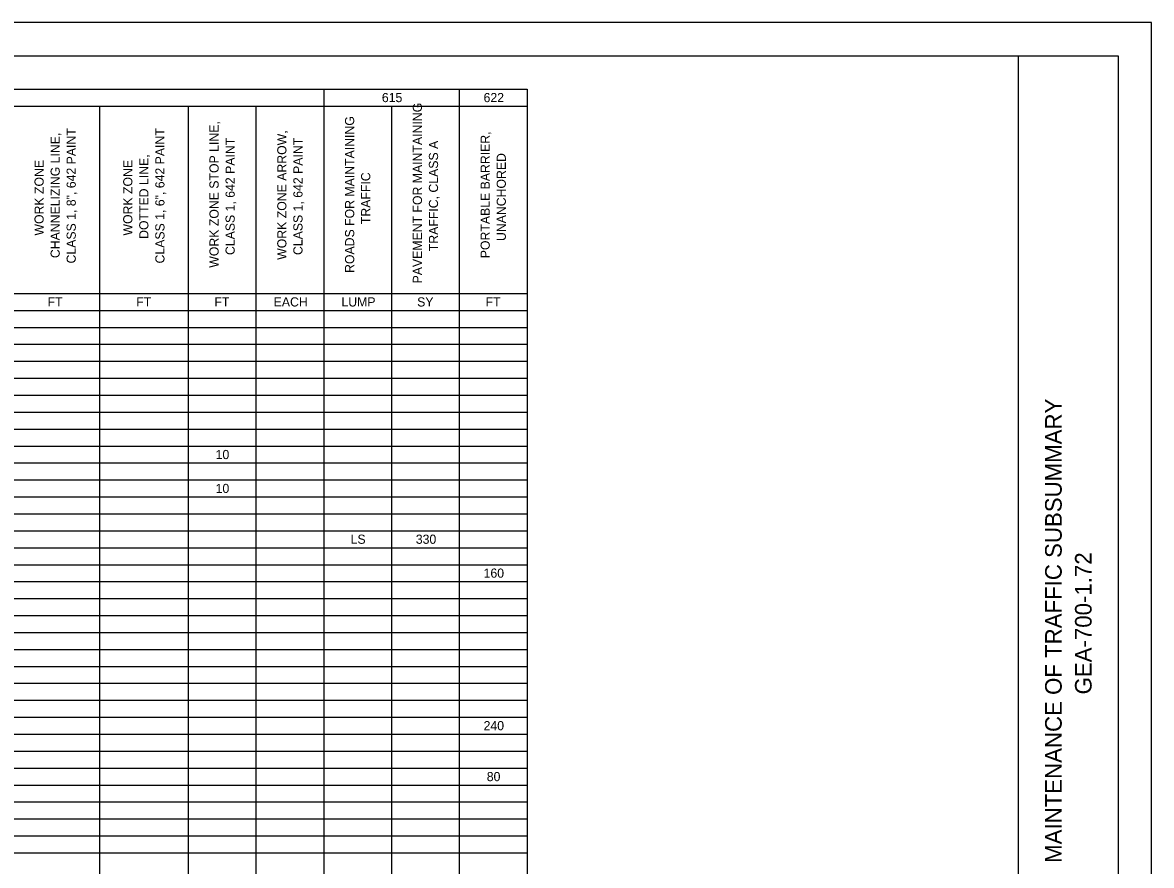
# Model space of a CAD drawing. Extents: x 0 to 34, y 0 to 22.
# Drawn here: x 17.01 to 34, y 9.32 to 22 of the extents above; entities that cross this region are included whole.
import ezdxf

# ---------------------------------------------------------------- set-up
doc = ezdxf.new("R2010")
doc.units = 0
for name, color, linetype in [('SH_Border', 7, 'Continuous'), ('SH_Cut_Line', 7, 'Continuous'), ('SH_Data', 7, 'Continuous'), ('SH_Text', 7, 'Continuous')]:
    doc.layers.add(name, color=color, linetype=linetype)

msp = doc.modelspace()

# ---------------------------------------------------------------- linework, layer by layer
at = {"layer": 'SH_Border'}
msp.add_line((32, 0.5), (32, 21.5), dxfattribs=at)
msp.add_lwpolyline([(1.5, 21.5), (33.5, 21.5), (33.5, 0.5), (1.5, 0.5)], close=True, dxfattribs=at)
at = {"layer": 'SH_Cut_Line'}
msp.add_lwpolyline([(0, 0), (34, 0), (34, 22), (0, 22)], close=True, dxfattribs=at)
at = {"layer": 'SH_Text'}
for p, q in [((2, 21), (24.605, 21)), ((21.545, 21), (21.545, 6.705)), ((23.585, 21), (23.585, 6.705)), ((24.605, 21), (24.605, 6.705)), ((8.045, 20.745), (24.605, 20.745)), ((18.17, 20.745), (18.17, 6.705)), ((19.505, 20.745), (19.505, 6.705)), ((20.525, 20.745), (20.525, 6.705)), ((22.565, 20.745), (22.565, 6.705)), ((8.045, 17.925), (24.605, 17.925)), ((2, 17.67), (24.605, 17.67)), ((2, 17.415), (24.605, 17.415)), ((2, 17.16), (24.605, 17.16)), ((2, 16.905), (24.605, 16.905)), ((2, 16.65), (24.605, 16.65)), ((2, 16.395), (24.605, 16.395)), ((2, 16.14), (24.605, 16.14)), ((2, 15.885), (24.605, 15.885)), ((2, 15.63), (24.605, 15.63)), ((2, 15.375), (24.605, 15.375)), ((2, 15.12), (24.605, 15.12)), ((2, 14.865), (24.605, 14.865)), ((2, 14.61), (24.605, 14.61)), ((2, 14.355), (24.605, 14.355)), ((2, 14.1), (24.605, 14.1)), ((2, 13.845), (24.605, 13.845)), ((2, 13.59), (24.605, 13.59)), ((2, 13.335), (24.605, 13.335)), ((2, 13.08), (24.605, 13.08)), ((2, 12.825), (24.605, 12.825)), ((2, 12.57), (24.605, 12.57)), ((2, 12.315), (24.605, 12.315)), ((2, 12.06), (24.605, 12.06)), ((2, 11.805), (24.605, 11.805)), ((2, 11.55), (24.605, 11.55)), ((2, 11.295), (24.605, 11.295)), ((2, 11.04), (24.605, 11.04)), ((2, 10.785), (24.605, 10.785)), ((2, 10.53), (24.605, 10.53)), ((2, 10.275), (24.605, 10.275)), ((2, 10.02), (24.605, 10.02)), ((2, 9.765), (24.605, 9.765)), ((2, 9.51), (24.605, 9.51))]:
    msp.add_line(p, q, dxfattribs=at)

# ---------------------------------------------------------------- texts
at = {"layer": 'SH_Data'}
for s, p in [('MAINTENANCE OF TRAFFIC SUBSUMMARY', (32.65, 9.359)), ('GEA-700-1.72', (33.1, 11.893))]:
    msp.add_text(s, height=0.25, rotation=90, dxfattribs=at).set_placement(p)
at = {"layer": 'SH_Text'}
for s, p in [('615', (22.419, 20.803)), ('622', (23.95, 20.803)), ('FT', (17.388, 17.729)), ('FT', (18.723, 17.729)), ('FT', (19.9, 17.729)), ('EACH', (20.791, 17.729)), ('LUMP', (21.811, 17.729)), ('SY', (22.95, 17.729)), ('FT', (23.98, 17.729)), ('10', (19.918, 15.433)), ('10', (19.918, 14.923)), ('LS', (21.949, 14.159)), ('330', (22.93, 14.159)), ('160', (23.95, 13.649)), ('240', (23.95, 11.354)), ('80', (23.998, 10.588))]:
    msp.add_text(s, height=0.138, dxfattribs=at).set_placement(p)
for s, p in [('PAVEMENT FOR MAINTAINING ', (23.023, 18.076)), ('ROADS FOR MAINTAINING ', (22.003, 18.234)), ('CLASS 1, 8", 642 PAINT', (17.813, 18.376)), ('CLASS 1, 6", 642 PAINT', (19.148, 18.376)), ('WORK ZONE STOP LINE, ', (19.963, 18.312)), ('CHANNELIZING LINE,', (17.572, 18.457)), ('CLASS 1, 642 PAINT', (20.205, 18.503)), ('WORK ZONE ARROW, ', (20.983, 18.431)), ('CLASS 1, 642 PAINT', (21.225, 18.503)), ('TRAFFIC, CLASS A', (23.265, 18.561)), ('PORTABLE BARRIER, ', (24.043, 18.455)), ('WORK ZONE', (17.33, 18.796)), ('WORK ZONE', (18.665, 18.796)), ('DOTTED LINE,', (18.906, 18.746)), ('UNANCHORED', (24.285, 18.714)), ('TRAFFIC', (22.245, 18.968))]:
    msp.add_text(s, height=0.138, rotation=90, dxfattribs=at).set_placement(p)

doc.saveas('drawing.dxf')
